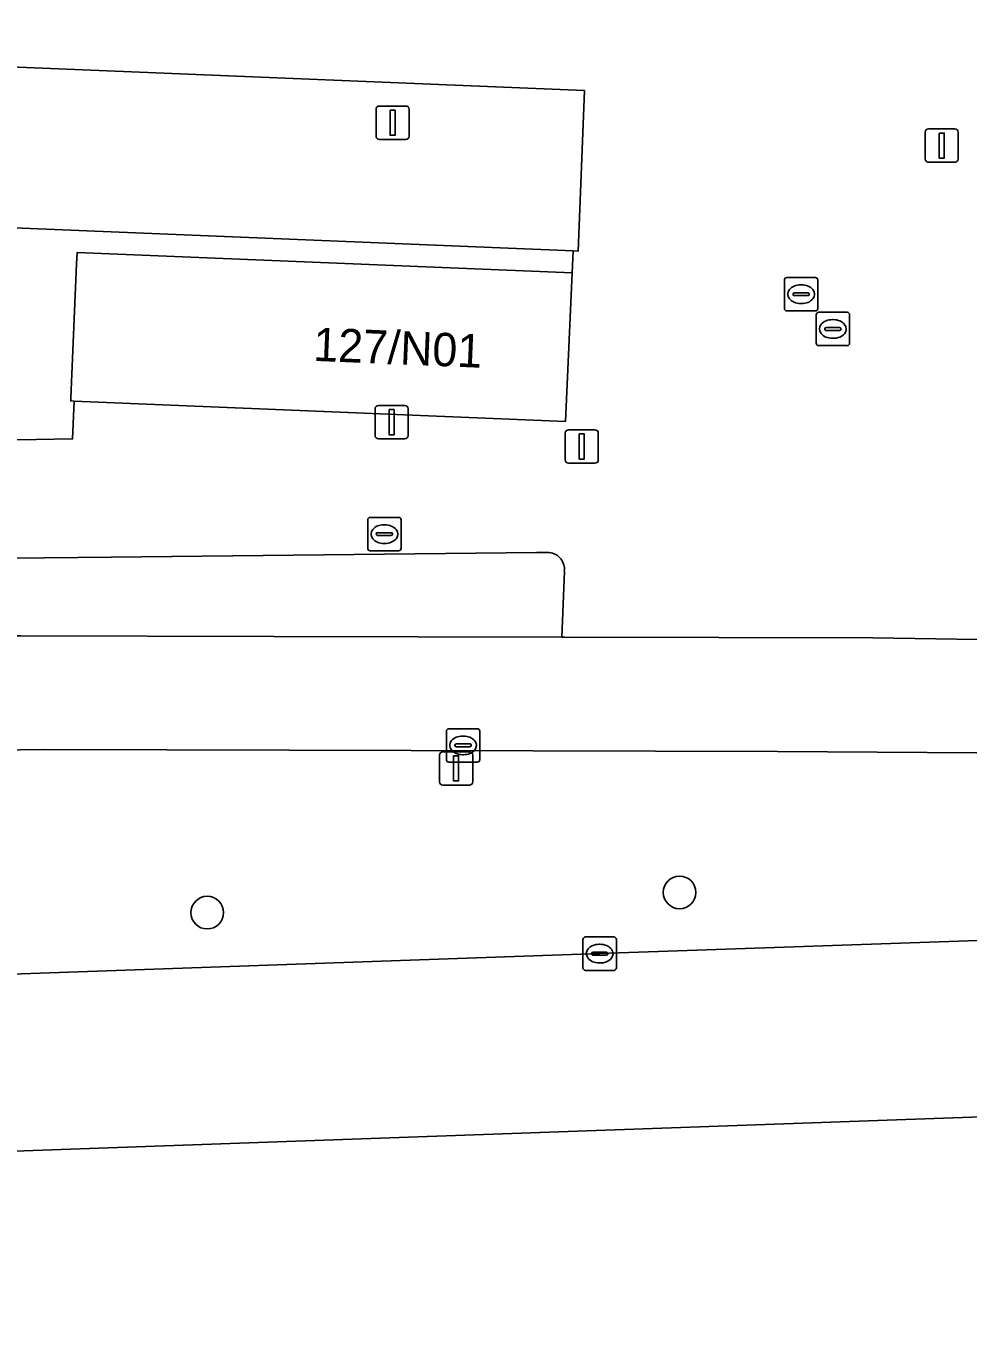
# Model space of a CAD drawing. Extents: x 160888 to 161385, y 386490 to 386908.
# Drawn here: x 161237.19 to 161265.41, y 386494.25 to 386533.16 of the extents above; entities that cross this region are included whole.
import ezdxf

# ---------------------------------------------------------------- set-up
doc = ezdxf.new("R2010")
doc.units = 0
for name, color, linetype in [('IMGEO_Berm_groen', 7, 'Continuous'), ('IMGEO_Boom', 7, 'Continuous'), ('IMGEO_Fietspad_gesloten', 7, 'Continuous'), ('IMGEO_Groenvoorziening', 7, 'Continuous'), ('IMGEO_Kolk', 7, 'Continuous'), ('IMGEO_Lichtmast', 7, 'Continuous'), ('IMGEO_Pand', 7, 'Continuous'), ('IMGEO_Pand_nummerreeks', 7, 'Continuous'), ('IMGEO_Parkeervlak_open', 7, 'Continuous'), ('IMGEO_Rijbaan_regionaal_gesloten', 7, 'Continuous'), ('IMGEO_Rioolput', 7, 'Continuous'), ('IMGEO_Voetgangersgebied_open', 7, 'Continuous'), ('IMGEO_Voetpad_open', 7, 'Continuous')]:
    doc.layers.add(name, color=color, linetype=linetype)

msp = doc.modelspace()

# ---------------------------------------------------------------- linework, layer by layer
at = {"layer": 'IMGEO_Berm_groen'}
for points in [[(161313.071, 386509.592), (161311.776, 386509.705), (161311.73, 386509.285), (161306.097, 386509.668), (161267.164, 386511.376), (161259.697, 386511.429), (161237.753, 386511.488), (161222.805, 386511.284), (161215.758, 386511.159), (161215.734, 386511.569), (161167.964, 386510.348), (161127.225, 386509.29)], [(161133.563, 386501.204), (161154.024, 386501.918), (161175.497, 386502.675), (161194.971, 386503.319), (161214.429, 386503.969), (161233.906, 386504.66), (161254.372, 386505.373), (161273.833, 386506.048), (161292.306, 386506.7), (161322.733, 386507.751)]]:
    msp.add_lwpolyline(points, dxfattribs=at)
at = {"layer": 'IMGEO_Boom'}
for centre in [(161256.765, 386507.206), (161242.616, 386506.601)]:
    msp.add_circle(centre, 0.489, dxfattribs=at)
at = {"layer": 'IMGEO_Fietspad_gesloten'}
for points in [[(161267.578, 386514.754), (161262.551, 386514.831), (161253.325, 386514.853), (161253.233, 386514.853), (161244.609, 386514.875), (161237.032, 386514.894), (161236.549, 386514.895), (161233.821, 386514.854), (161231.599, 386514.82), (161230.845, 386514.809), (161227.787, 386514.763), (161226.292, 386514.741), (161221.75, 386514.672), (161219.333, 386514.636), (161214.527, 386514.564), (161214.131, 386514.554), (161212.923, 386514.523), (161205.423, 386514.331), (161205.404, 386514.331), (161197.221, 386514.122)], [(161106.833, 386506.491), (161109.839, 386506.955), (161116.836, 386508.035), (161123.035, 386508.931), (161127.225, 386509.29), (161167.964, 386510.348), (161215.734, 386511.569), (161215.758, 386511.159), (161222.805, 386511.284), (161237.753, 386511.488), (161259.697, 386511.429), (161267.164, 386511.376), (161306.097, 386509.668), (161311.73, 386509.285), (161311.776, 386509.705), (161313.071, 386509.592)]]:
    msp.add_lwpolyline(points, dxfattribs=at)
at = {"layer": 'IMGEO_Groenvoorziening'}
for points in [[(161252.863, 386517.39), (161252.478, 386517.39), (161239.735, 386517.251), (161233.722, 386517.186), (161221.767, 386517.056), (161206.921, 386516.896), (161206.016, 386516.884), (161205.917, 386516.886), (161205.844, 386516.883)], [(161205.404, 386514.331), (161205.423, 386514.331), (161212.923, 386514.523), (161214.131, 386514.554), (161214.527, 386514.564), (161219.333, 386514.636), (161221.75, 386514.672), (161226.292, 386514.741), (161227.787, 386514.763), (161230.845, 386514.809), (161231.599, 386514.82), (161233.821, 386514.854), (161236.549, 386514.895), (161237.032, 386514.894), (161244.609, 386514.875), (161253.233, 386514.853), (161253.313, 386516.825)]]:
    msp.add_lwpolyline(points, dxfattribs=at)
msp.add_arc((161252.806, 386516.883), 0.51, 353.443, 83.6289, dxfattribs=at)
at = {"layer": 'IMGEO_Kolk'}
for p, q in [((161259.905, 386524.698), (161259.905, 386525.55)), ((161259.98, 386525.624), (161260.832, 386525.624)), ((161260.393, 386525.404), (161260.418, 386525.404)), ((161260.906, 386525.55), (161260.906, 386524.698)), ((161260.164, 386525.118), (161260.164, 386525.13)), ((161260.602, 386525.081), (161260.204, 386525.081)), ((161260.207, 386525.167), (161260.605, 386525.167)), ((161260.648, 386525.13), (161260.648, 386525.118)), ((161260.832, 386524.624), (161259.98, 386524.624)), ((161260.416, 386524.844), (161260.391, 386524.844)), ((161247.422, 386517.513), (161247.422, 386518.365)), ((161247.497, 386518.439), (161248.349, 386518.439)), ((161248.423, 386518.365), (161248.423, 386517.513)), ((161247.681, 386517.933), (161247.681, 386517.945)), ((161247.724, 386517.982), (161248.122, 386517.982)), ((161247.91, 386518.219), (161247.935, 386518.219)), ((161248.165, 386517.945), (161248.165, 386517.933)), ((161248.119, 386517.896), (161247.721, 386517.896)), ((161247.933, 386517.659), (161247.908, 386517.659)), ((161248.349, 386517.439), (161247.497, 386517.439)), ((161249.853, 386512.111), (161250.705, 386512.111)), ((161249.778, 386511.185), (161249.778, 386512.037)), ((161250.266, 386511.891), (161250.291, 386511.891)), ((161250.779, 386512.037), (161250.779, 386511.185)), ((161250.037, 386511.605), (161250.037, 386511.617)), ((161250.475, 386511.568), (161250.077, 386511.568)), ((161250.08, 386511.654), (161250.478, 386511.654)), ((161250.289, 386511.331), (161250.264, 386511.331)), ((161250.521, 386511.617), (161250.521, 386511.605)), ((161250.705, 386511.111), (161249.853, 386511.111)), ((161253.946, 386505.873), (161254.798, 386505.873)), ((161253.871, 386504.947), (161253.871, 386505.799)), ((161254.359, 386505.653), (161254.384, 386505.653)), ((161254.872, 386505.799), (161254.872, 386504.947)), ((161254.13, 386505.367), (161254.13, 386505.379)), ((161254.568, 386505.33), (161254.17, 386505.33)), ((161254.173, 386505.416), (161254.571, 386505.416)), ((161254.382, 386505.093), (161254.357, 386505.093)), ((161254.614, 386505.379), (161254.614, 386505.367)), ((161254.798, 386504.873), (161253.946, 386504.873))]:
    msp.add_line(p, q, dxfattribs=at)
for points in [[(161259.905, 386524.698), (161259.905, 386525.55)], [(161259.98, 386525.624), (161260.832, 386525.624)], [(161260.906, 386525.55), (161260.906, 386524.698)], [(161260.832, 386524.624), (161259.98, 386524.624)], [(161247.422, 386517.513), (161247.422, 386518.365)], [(161247.497, 386518.439), (161248.349, 386518.439)], [(161248.423, 386518.365), (161248.423, 386517.513)], [(161248.349, 386517.439), (161247.497, 386517.439)], [(161249.853, 386512.111), (161250.705, 386512.111)], [(161249.778, 386511.185), (161249.778, 386512.037)], [(161250.779, 386512.037), (161250.779, 386511.185)], [(161250.705, 386511.111), (161249.853, 386511.111)], [(161253.946, 386505.873), (161254.798, 386505.873)], [(161253.871, 386504.947), (161253.871, 386505.799)], [(161254.872, 386505.799), (161254.872, 386504.947)], [(161254.798, 386504.873), (161253.946, 386504.873)]]:
    msp.add_lwpolyline(points, dxfattribs=at)
for centre, radius, start, end in [((161259.982, 386525.548), 0.0765, 91.552, 178.448), ((161259.982, 386525.548), 0.0765, 91.552, 178.448), ((161260.83, 386525.548), 0.0765, 1.552, 88.448), ((161260.83, 386525.548), 0.0765, 1.552, 88.448), ((161260.204, 386525.127), 0.0403, 85.8775, 175.7526), ((161260.201, 386525.117), 0.0366, 178.938, 274.7102), ((161260.605, 386525.124), 0.043, 264.8664, 352.4533), ((161260.609, 386525.129), 0.0386, 1.7309, 96.639), ((161259.982, 386524.7), 0.0765, 181.552, 268.448), ((161259.982, 386524.7), 0.0765, 181.552, 268.448), ((161260.83, 386524.7), 0.0765, 271.552, 358.448), ((161260.83, 386524.7), 0.0765, 271.552, 358.448), ((161247.499, 386518.363), 0.0765, 91.552, 178.448), ((161247.499, 386518.363), 0.0765, 91.552, 178.448), ((161248.347, 386518.363), 0.0765, 1.552, 88.448), ((161248.347, 386518.363), 0.0765, 1.552, 88.448), ((161247.721, 386517.942), 0.0403, 85.8775, 175.7526), ((161247.718, 386517.932), 0.0366, 178.938, 274.7102), ((161248.122, 386517.939), 0.043, 264.8664, 352.4533), ((161248.126, 386517.944), 0.0386, 1.7309, 96.639), ((161247.499, 386517.515), 0.0765, 181.552, 268.448), ((161247.499, 386517.515), 0.0765, 181.552, 268.448), ((161248.347, 386517.515), 0.0765, 271.552, 358.448), ((161248.347, 386517.515), 0.0765, 271.552, 358.448), ((161249.855, 386512.035), 0.0765, 91.552, 178.448), ((161249.855, 386512.035), 0.0765, 91.552, 178.448), ((161250.703, 386512.035), 0.0765, 1.552, 88.448), ((161250.703, 386512.035), 0.0765, 1.552, 88.448), ((161250.077, 386511.614), 0.0403, 85.8775, 175.7526), ((161250.074, 386511.604), 0.0366, 178.938, 274.7102), ((161250.478, 386511.611), 0.043, 264.8664, 352.4533), ((161250.482, 386511.616), 0.0386, 1.7309, 96.639), ((161249.855, 386511.187), 0.0765, 181.552, 268.448), ((161249.855, 386511.187), 0.0765, 181.552, 268.448), ((161250.703, 386511.187), 0.0765, 271.552, 358.448), ((161250.703, 386511.187), 0.0765, 271.552, 358.448), ((161253.948, 386505.797), 0.0765, 91.552, 178.448), ((161253.948, 386505.797), 0.0765, 91.552, 178.448), ((161254.796, 386505.797), 0.0765, 1.552, 88.448), ((161254.796, 386505.797), 0.0765, 1.552, 88.448), ((161254.17, 386505.376), 0.0403, 85.8775, 175.7526), ((161254.167, 386505.366), 0.0366, 178.938, 274.7102), ((161254.571, 386505.373), 0.043, 264.8664, 352.4533), ((161254.575, 386505.378), 0.0386, 1.7309, 96.639), ((161253.948, 386504.949), 0.0765, 181.552, 268.448), ((161253.948, 386504.949), 0.0765, 181.552, 268.448), ((161254.796, 386504.949), 0.0765, 271.552, 358.448), ((161254.796, 386504.949), 0.0765, 271.552, 358.448)]:
    msp.add_arc(centre, radius, start, end, dxfattribs=at)
for centre, major_axis, ratio, start_param, end_param in [((161260.392, 386525.124), (-0.387, 0.002), 0.722429, 4.712389, 7.853982), ((161260.417, 386525.124), (-0.39, 0.002), 0.717154, 1.570796, 4.712389), ((161247.909, 386517.939), (-0.387, 0.002), 0.722429, 4.712389, 7.853982), ((161247.934, 386517.939), (-0.39, 0.002), 0.717154, 1.570796, 4.712389), ((161250.265, 386511.611), (-0.387, 0.002), 0.722429, 4.712389, 7.853982), ((161250.29, 386511.611), (-0.39, 0.002), 0.717154, 1.570796, 4.712389), ((161254.358, 386505.373), (-0.387, 0.002), 0.722429, 4.712389, 7.853982), ((161254.383, 386505.373), (-0.39, 0.002), 0.717154, 1.570796, 4.712389)]:
    msp.add_ellipse(centre, major_axis=major_axis, ratio=ratio, start_param=start_param, end_param=end_param, dxfattribs=at)
at = {"layer": 'IMGEO_Lichtmast'}
for p, q in [((161247.773, 386530.761), (161248.563, 386530.761)), ((161248.563, 386530.761), (161247.773, 386530.761)), ((161247.673, 386529.861), (161247.673, 386530.661)), ((161247.673, 386530.661), (161247.673, 386529.861)), ((161248.663, 386530.661), (161248.663, 386529.861)), ((161248.663, 386529.861), (161248.663, 386530.661)), ((161264.121, 386529.175), (161264.121, 386529.975)), ((161264.121, 386529.975), (161264.121, 386529.175)), ((161264.221, 386530.075), (161265.011, 386530.075)), ((161265.011, 386530.075), (161264.221, 386530.075)), ((161265.111, 386529.975), (161265.111, 386529.175)), ((161265.111, 386529.175), (161265.111, 386529.975)), ((161248.563, 386529.761), (161247.773, 386529.761)), ((161247.773, 386529.761), (161248.563, 386529.761)), ((161265.011, 386529.075), (161264.221, 386529.075)), ((161264.221, 386529.075), (161265.011, 386529.075)), ((161247.642, 386520.892), (161247.642, 386521.692)), ((161247.642, 386521.692), (161247.642, 386520.892)), ((161247.742, 386521.792), (161248.532, 386521.792)), ((161248.532, 386521.792), (161247.742, 386521.792)), ((161248.632, 386521.692), (161248.632, 386520.892)), ((161248.632, 386520.892), (161248.632, 386521.692)), ((161253.441, 386521.063), (161254.231, 386521.063)), ((161254.231, 386521.063), (161253.441, 386521.063)), ((161248.532, 386520.792), (161247.742, 386520.792)), ((161247.742, 386520.792), (161248.532, 386520.792)), ((161253.341, 386520.163), (161253.341, 386520.963)), ((161253.341, 386520.963), (161253.341, 386520.163)), ((161254.331, 386520.963), (161254.331, 386520.163)), ((161254.331, 386520.163), (161254.331, 386520.963)), ((161254.231, 386520.063), (161253.441, 386520.063)), ((161253.441, 386520.063), (161254.231, 386520.063)), ((161249.577, 386510.52), (161249.577, 386511.32)), ((161249.577, 386511.32), (161249.577, 386510.52)), ((161249.677, 386511.42), (161250.467, 386511.42)), ((161250.467, 386511.42), (161249.677, 386511.42)), ((161250.567, 386511.32), (161250.567, 386510.52)), ((161250.567, 386510.52), (161250.567, 386511.32)), ((161250.467, 386510.42), (161249.677, 386510.42)), ((161249.677, 386510.42), (161250.467, 386510.42))]:
    msp.add_line(p, q, dxfattribs=at)
for points in [[(161248.093, 386530.636), (161248.243, 386530.636), (161248.243, 386529.886), (161248.093, 386529.886), (161248.093, 386530.636)], [(161264.541, 386529.95), (161264.691, 386529.95), (161264.691, 386529.2), (161264.541, 386529.2), (161264.541, 386529.95)], [(161248.062, 386521.667), (161248.212, 386521.667), (161248.212, 386520.917), (161248.062, 386520.917), (161248.062, 386521.667)], [(161253.761, 386520.938), (161253.911, 386520.938), (161253.911, 386520.188), (161253.761, 386520.188), (161253.761, 386520.938)], [(161249.997, 386511.295), (161250.147, 386511.295), (161250.147, 386510.545), (161249.997, 386510.545), (161249.997, 386511.295)]]:
    msp.add_lwpolyline(points, dxfattribs=at)
for centre, start, end in [((161247.773, 386530.661), 90, 180), ((161247.773, 386530.661), 90, 180), ((161248.563, 386530.661), 0, 90), ((161248.563, 386530.661), 360, 90), ((161264.221, 386529.975), 90, 180), ((161264.221, 386529.975), 90, 180), ((161265.011, 386529.975), 0, 90), ((161265.011, 386529.975), 360, 90), ((161247.773, 386529.861), 180, 270), ((161247.773, 386529.861), 180, 270), ((161248.563, 386529.861), 270, 0), ((161248.563, 386529.861), 270, 0), ((161264.221, 386529.175), 180, 270), ((161264.221, 386529.175), 180, 270), ((161265.011, 386529.175), 270, 0), ((161265.011, 386529.175), 270, 0), ((161247.742, 386521.692), 90, 180), ((161247.742, 386521.692), 90, 180), ((161248.532, 386521.692), 0, 90), ((161248.532, 386521.692), 360, 90), ((161253.441, 386520.963), 90, 180), ((161253.441, 386520.963), 90, 180), ((161254.231, 386520.963), 0, 90), ((161254.231, 386520.963), 360, 90), ((161247.742, 386520.892), 180, 270), ((161247.742, 386520.892), 180, 270), ((161248.532, 386520.892), 270, 0), ((161248.532, 386520.892), 270, 0), ((161253.441, 386520.163), 180, 270), ((161253.441, 386520.163), 180, 270), ((161254.231, 386520.163), 270, 0), ((161254.231, 386520.163), 270, 0), ((161249.677, 386511.32), 90, 180), ((161249.677, 386511.32), 90, 180), ((161250.467, 386511.32), 0, 90), ((161250.467, 386511.32), 360, 90), ((161249.677, 386510.52), 180, 270), ((161249.677, 386510.52), 180, 270), ((161250.467, 386510.52), 270, 0), ((161250.467, 386510.52), 270, 0)]:
    msp.add_arc(centre, 0.1, start, end, dxfattribs=at)
at = {"layer": 'IMGEO_Pand'}
msp.add_lwpolyline([(161253.549, 386525.76), (161238.718, 386526.371), (161238.703, 386526.033), (161238.531, 386522.021), (161238.527, 386521.927), (161238.627, 386521.923), (161253.343, 386521.315)], close=True, dxfattribs=at)
at = {"layer": 'IMGEO_Parkeervlak_open'}
msp.add_lwpolyline([(161253.921, 386531.225), (161220.471, 386532.599), (161220.36, 386529.791), (161221.46, 386529.753), (161221.376, 386527.753), (161236.584, 386527.124), (161253.58, 386526.42), (161253.732, 386526.414)], close=True, dxfattribs=at)
at = {"layer": 'IMGEO_Rijbaan_regionaal_gesloten'}
msp.add_lwpolyline([(161083.554, 386494.25), (161197.468, 386498.064), (161264.673, 386500.448), (161323.284, 386502.509), (161323.08, 386507.769), (161322.733, 386507.751), (161292.306, 386506.7), (161273.833, 386506.048), (161254.372, 386505.373), (161233.906, 386504.66), (161214.429, 386503.969), (161194.971, 386503.319), (161175.497, 386502.675), (161154.024, 386501.918), (161133.563, 386501.204)], dxfattribs=at)
at = {"layer": 'IMGEO_Rioolput'}
for p, q in [((161260.932, 386524.583), (161261.784, 386524.583)), ((161260.857, 386523.657), (161260.857, 386524.509)), ((161261.345, 386524.363), (161261.37, 386524.363)), ((161261.858, 386524.509), (161261.858, 386523.657)), ((161261.116, 386524.077), (161261.116, 386524.089)), ((161261.554, 386524.04), (161261.156, 386524.04)), ((161261.159, 386524.126), (161261.557, 386524.126)), ((161261.368, 386523.803), (161261.343, 386523.803)), ((161261.6, 386524.089), (161261.6, 386524.077)), ((161261.784, 386523.583), (161260.932, 386523.583))]:
    msp.add_line(p, q, dxfattribs=at)
for points in [[(161260.932, 386524.583), (161261.784, 386524.583)], [(161260.857, 386523.657), (161260.857, 386524.509)], [(161261.858, 386524.509), (161261.858, 386523.657)], [(161261.784, 386523.583), (161260.932, 386523.583)]]:
    msp.add_lwpolyline(points, dxfattribs=at)
for centre, radius, start, end in [((161260.934, 386524.507), 0.0765, 91.552, 178.448), ((161260.934, 386524.507), 0.0765, 91.552, 178.448), ((161261.782, 386524.507), 0.0765, 1.552, 88.448), ((161261.782, 386524.507), 0.0765, 1.552, 88.448), ((161261.156, 386524.086), 0.0403, 85.8775, 175.7526), ((161261.153, 386524.076), 0.0366, 178.938, 274.7102), ((161261.557, 386524.083), 0.043, 264.8664, 352.4533), ((161261.561, 386524.088), 0.0386, 1.7309, 96.639), ((161260.934, 386523.659), 0.0765, 181.552, 268.448), ((161260.934, 386523.659), 0.0765, 181.552, 268.448), ((161261.782, 386523.659), 0.0765, 271.552, 358.448), ((161261.782, 386523.659), 0.0765, 271.552, 358.448)]:
    msp.add_arc(centre, radius, start, end, dxfattribs=at)
for centre, major_axis, ratio, start_param, end_param in [((161261.344, 386524.083), (-0.387, 0.002), 0.722429, 4.712389, 7.853982), ((161261.369, 386524.083), (-0.39, 0.002), 0.717154, 1.570796, 4.712389)]:
    msp.add_ellipse(centre, major_axis=major_axis, ratio=ratio, start_param=start_param, end_param=end_param, dxfattribs=at)
at = {"layer": 'IMGEO_Voetgangersgebied_open'}
msp.add_lwpolyline([(161253.921, 386531.225), (161253.732, 386526.414), (161253.58, 386526.42), (161253.549, 386525.76), (161253.343, 386521.315), (161238.627, 386521.923), (161238.58, 386520.79), (161237.489, 386520.777), (161236.366, 386520.764), (161227.455, 386520.659), (161205.859, 386520.404), (161205.979, 386522.969), (161206.385, 386533.158), (161220.471, 386532.599)], close=True, dxfattribs=at)
for points in [[(161205.844, 386516.883), (161205.917, 386516.886), (161206.016, 386516.884), (161206.921, 386516.896), (161221.767, 386517.056), (161233.722, 386517.186), (161239.735, 386517.251), (161252.478, 386517.39), (161252.863, 386517.39)], [(161253.313, 386516.825), (161253.233, 386514.853), (161253.325, 386514.853), (161262.551, 386514.831), (161267.578, 386514.754), (161306.554, 386513.058)]]:
    msp.add_lwpolyline(points, dxfattribs=at)
msp.add_arc((161252.806, 386516.883), 0.51, 353.443, 83.6289, dxfattribs=at)
at = {"layer": 'IMGEO_Voetpad_open'}
msp.add_lwpolyline([(161253.58, 386526.42), (161236.584, 386527.124), (161236.579, 386526.123), (161236.452, 386522.922), (161236.404, 386521.716), (161236.366, 386520.764), (161237.489, 386520.777), (161238.58, 386520.79), (161238.627, 386521.923), (161238.527, 386521.927), (161238.531, 386522.021), (161238.703, 386526.033), (161238.718, 386526.371), (161253.549, 386525.76)], close=True, dxfattribs=at)

# ---------------------------------------------------------------- texts
at = {"layer": 'IMGEO_Pand_nummerreeks'}
msp.add_text('127/N01', height=1, rotation=357.6337, dxfattribs=at).set_placement((161245.778, 386523.129))

doc.saveas('drawing.dxf')
